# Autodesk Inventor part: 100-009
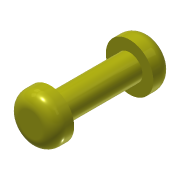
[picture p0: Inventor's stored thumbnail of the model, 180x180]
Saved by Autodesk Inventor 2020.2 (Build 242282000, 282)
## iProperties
Created: 2014-01
Part Number: 100-009
Material: Ogólny
Document SubType Name: Modeling
Designer: F.Stasiak
Density: 1 g/cm^3
Appearance: Żółta
Manager: www.cadconsulting.pl
Company: Fabian Stasiak CAD Consulting
Author: F.Stasiak
Subject: Zbiór ćwiczeń. Autodesk Inventor 2020. Kurs podstawowy
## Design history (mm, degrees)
sketch "Szkic1"
  geometry: C1 r 3.25 at (0, 0); 1 further point
  constraints: 1 centre point, 1 coincident
  dimensions: "d0" = 6.5 diameter of C1
extrude "Wyciągnięcie proste1" new body sketch "Szkic1" distance "d1" = 10; taper "d2" = 0 deg
sketch "Szkic2"
  geometry: C1 r 3.25 at (0, 0) reference; C2 r 6 at (0, 0)
  constraints: 1 centre point, 1 coincident
  dimensions: "d3" = 12 diameter of C2
extrude "Wyciągnięcie proste2" join sketch "Szkic2" distance "d4" = 5; taper "d5" = 0 deg
fillet "Zaokrąglenie1" dims "d6" = 3
mirror "Odbicie lustrzane1"
node "Bryła1"
